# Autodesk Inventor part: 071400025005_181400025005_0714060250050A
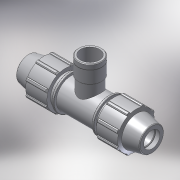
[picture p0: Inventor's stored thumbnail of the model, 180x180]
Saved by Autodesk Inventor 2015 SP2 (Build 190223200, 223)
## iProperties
Created: 2017-02
Part Number: 071400025005_181400025005_0714060250050A
Material: PVC-Piping
Description: PLASSON TEE WITH THREADED FEMALE OFFTAKE 25-1/2"-25
Document SubType Name: Modeling
Designer: KIM
Mass: 92.6774 g
Surface Area: 199.44 cm^2
Volume: 66.1981 cm^3
Density: 1.4 g/cm^3
Appearance: Smooth - White
Author: KIM
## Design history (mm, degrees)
derived "07140.ipt"
feature "Solid1::07140.ipt"
feature "Solid2::07140.ipt"
tag "TaggingFeature1"
body "Solid1"
other parameters: "d2" = 25, "d4" = 6.29167, "d5" = 18.12, "d7" = 54, "d11" = 2.51667, "d13" = 120 deg, "d14" = 37.5, "d15" = 12 deg, "d16" = 46.98, "d18" = 1.25, "d19" = 35 deg, "d20" = 17.5 deg, "d21" = 50.22, "d23" = 0, "d25" = 360 deg, "d27" = 1.08, "d33" = 0.5, "d42" = 27.18, "d43" = 1.62, "d46" = 0.75, "d68" = 4.53, "d72" = 45, "d76" = 18.631, "d80" = 0.55893, "d91" = 40.5, "d93" = 58, "d95" = 22.5, "d112" = 18, "d115" = 23.28875, "d116" = 135 deg, "d117" = 21.42565, "d118" = 151, "d119" = 22.5, "d121" = 0, "d122" = 15.75, "d124" = 0, "d128" = 0, "d129" = 2.5, "d130" = 5.4, "d131" = 0.3, "d132" = 0.3, "d133" = 23.28875, "d_" = 25, "E_" = 54, "A_" = 45, "l_" = 58, "l_2" = 18, "Rp_" = 18.631, "H_" = 151
